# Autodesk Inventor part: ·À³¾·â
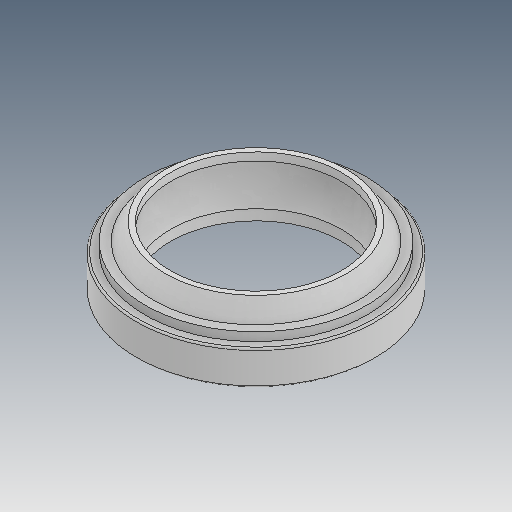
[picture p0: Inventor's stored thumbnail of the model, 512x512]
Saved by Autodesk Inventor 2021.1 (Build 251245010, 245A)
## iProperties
Created: 2013-04
Part Number: ·À³¾·â
Material: Ogólny
Document SubType Name: Modeling
Designer: user
Density: 1 g/cm^3
Appearance: Domyślna
Author: user
Revision Number: ÈÎºÎ
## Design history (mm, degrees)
feature "Ðý×ª1"
node "Bryła1"
